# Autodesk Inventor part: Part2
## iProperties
Shininess: 64.0
Length Units: 11269
Angle Units: 11279
Time Units: 11290
Mass Units: 11283
Length Display Precision: 3
Angle Display Precision: 2
Compacted: True
Part Number: Part2
Document SubType Name: Modeling
Created: 2004-08
Designer: John Blackburn
Manufacturer: Standard
Standards Organization: Custom
Density: 0.0
Volumn: 0.0
Area: 0.0
PropertySet Name: Model Information
Control State: 0
Master: False
Checked Out: False
Author: John Blackburn
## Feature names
1. Extrusion1
